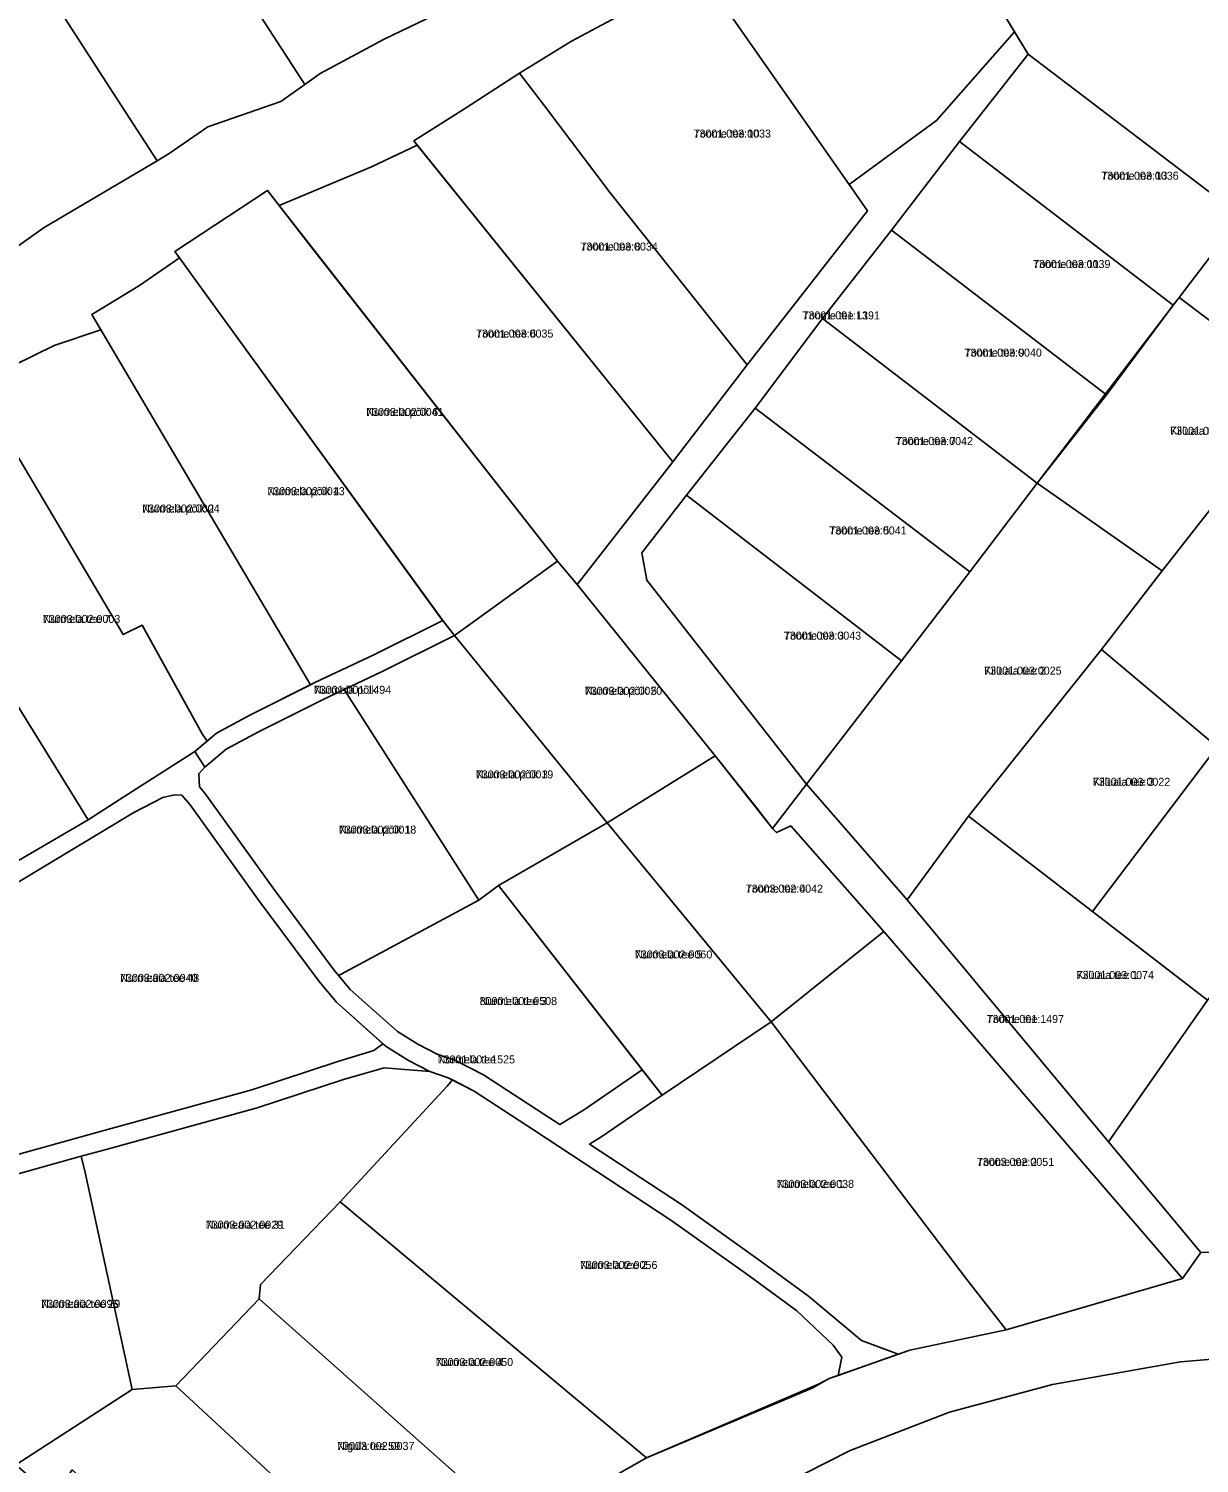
# Model space of a CAD drawing. Extents: x 524000 to 564260, y 6469338 to 6496391.
# Drawn here: x 527061.2 to 527280.6, y 6477525.9 to 6477794.8 of the extents above; entities that cross this region are included whole.
import ezdxf

# ---------------------------------------------------------------- set-up
doc = ezdxf.new("R2010")
doc.units = 0
for name, color, linetype in [('L_AADRESS', 7, 'Continuous'), ('PIIR', 7, 'Continuous'), ('TUNNUS', 7, 'Continuous')]:
    doc.layers.add(name, color=color, linetype=linetype)

msp = doc.modelspace()

# ---------------------------------------------------------------- linework, layer by layer
at = {"layer": 'PIIR'}
for points in [[(527068.69, 6477906.14), (527130.5, 6477810.53), (527138.62, 6477797.97), (527127.79, 6477792.82), (527115.83, 6477786.37), (527112.92, 6477784.31), (527104.79, 6477796.89), (527045.95, 6477887.9)], [(527045.95, 6477887.9), (527104.79, 6477796.89), (527112.92, 6477784.31), (527108.42, 6477781.12), (527094.74, 6477776.35), (527087.52, 6477771.35), (527085.25, 6477770.01), (527077.11, 6477782.59), (527021.72, 6477868.28)], [(527021.72, 6477868.28), (527077.11, 6477782.59), (527085.25, 6477770.01), (527064.12, 6477757.5), (527057.25, 6477752.65), (527056.18, 6477751.87), (527048.35, 6477764.63), (526997.09, 6477848.14)], [(527266.58, 6477860.55), (527270.02, 6477853.57), (527305.23, 6477782.18), (527288.4, 6477759.62), (527248.48, 6477789.96), (527229.03, 6477822.06), (527224.3, 6477829.87)], [(527224.3, 6477829.87), (527229.03, 6477822.06), (527245.93, 6477794.14), (527231.3, 6477777.56), (527214.95, 6477765.58), (527190.7, 6477800.22), (527187.28, 6477805.1), (527195.12, 6477809.32), (527210.56, 6477819.4)], [(527187.28, 6477805.1), (527190.7, 6477800.22), (527214.95, 6477765.58), (527218.37, 6477760.64), (527195.82, 6477731.76), (527170.17, 6477763.97), (527157.85, 6477780.28), (527153.2, 6477786.44), (527162.89, 6477792.39), (527171.34, 6477796.93)], [(527189.84, 6477658.5), (527163.95, 6477690.58), (527181.89, 6477713.57), (527195.82, 6477731.76), (527218.37, 6477760.64), (527214.95, 6477765.58), (527231.3, 6477777.56), (527245.93, 6477794.14), (527248.48, 6477789.96), (527235.64, 6477773.63), (527222.86, 6477757.03), (527209.95, 6477740.46), (527197.34, 6477723.64), (527184.5, 6477707.33), (527176.12, 6477696.54), (527177.03, 6477691.41), (527206.94, 6477653.19), (527200.56, 6477644.84), (527197.69, 6477648.62)], [(527248.48, 6477789.96), (527288.4, 6477759.62), (527276.79, 6477744.38), (527275.7, 6477742.96), (527235.64, 6477773.63)], [(527143.07, 6477779.88), (527153.2, 6477786.44), (527157.85, 6477780.28), (527170.17, 6477763.97), (527195.82, 6477731.76), (527181.89, 6477713.57), (527133.36, 6477773.72)], [(527305.23, 6477782.18), (527324.08, 6477757.66), (527300.02, 6477726.9), (527276.79, 6477744.38), (527288.4, 6477759.62)], [(527125.43, 6477768.89), (527133.99, 6477772.93), (527181.89, 6477713.57), (527163.95, 6477690.58), (527160.28, 6477694.97), (527108.15, 6477761.62)], [(527235.64, 6477773.63), (527275.7, 6477742.96), (527263.16, 6477726.16), (527222.86, 6477757.03)], [(527088.6, 6477753.02), (527105.94, 6477764.46), (527113.9, 6477754.21), (527160.28, 6477694.97), (527140.98, 6477681.05), (527138.46, 6477684.3), (527093.32, 6477746.47)], [(527222.86, 6477757.03), (527263.16, 6477726.16), (527250.21, 6477709.58), (527209.95, 6477740.46)], [(527081.95, 6477746.64), (527089.44, 6477751.81), (527093.32, 6477746.47), (527138.8, 6477683.87), (527125.88, 6477677.42), (527114.82, 6477672.2), (527114.02, 6477671.8), (527076.07, 6477736.03), (527073.02, 6477741.2)], [(527250.21, 6477709.58), (527276.79, 6477744.38), (527300.02, 6477726.9), (527288.08, 6477711.67), (527273.59, 6477693.17)], [(527209.95, 6477740.46), (527250.21, 6477709.58), (527237.54, 6477692.99), (527197.34, 6477723.64)], [(527050.91, 6477728.01), (527065.98, 6477735.39), (527074.71, 6477738.34), (527076.07, 6477736.03), (527114.02, 6477671.8), (527102.76, 6477666.17), (527096.41, 6477662.75), (527094.62, 6477661.25), (527093.73, 6477662.6), (527082.49, 6477682.97), (527078.87, 6477681.22), (527055.88, 6477720.07)], [(527033.11, 6477709.77), (527037.79, 6477712.63), (527045.06, 6477726.1), (527049.58, 6477730.12), (527055.88, 6477720.07), (527078.87, 6477681.22), (527082.49, 6477682.97), (527093.73, 6477662.6), (527094.62, 6477661.25), (527092.3, 6477659.3), (527079.19, 6477650.92), (527072.35, 6477646.49), (527035.82, 6477705.55)], [(527197.34, 6477723.64), (527237.54, 6477692.99), (527224.78, 6477676.3), (527184.5, 6477707.33)], [(527012.25, 6477696.65), (527016.89, 6477699.87), (527033.11, 6477709.77), (527035.82, 6477705.55), (527072.35, 6477646.49), (527051.39, 6477634.3), (527015.45, 6477691.74)], [(527273.59, 6477693.17), (527288.08, 6477711.67), (527309.2, 6477692.83), (527284.7, 6477661.21), (527283.91, 6477660.2), (527262.26, 6477678.4)], [(527176.12, 6477696.54), (527184.5, 6477707.33), (527224.78, 6477676.3), (527206.94, 6477653.19), (527177.03, 6477691.41)], [(527273.59, 6477693.17), (527262.26, 6477678.4), (527237.33, 6477647.17), (527225.84, 6477631.5), (527206.94, 6477653.19), (527224.78, 6477676.3), (527237.54, 6477692.99), (527250.21, 6477709.58)], [(527140.98, 6477681.05), (527160.28, 6477694.97), (527163.95, 6477690.58), (527189.84, 6477658.5), (527169.63, 6477645.9)], [(527094.19, 6477656.35), (527092.3, 6477659.3), (527096.41, 6477662.75), (527102.76, 6477666.17), (527114.82, 6477672.2), (527125.88, 6477677.42), (527138.8, 6477683.87), (527140.98, 6477681.05), (527127.41, 6477674.27), (527116.35, 6477669.05), (527104.37, 6477663.07), (527098.23, 6477659.76)], [(527140.98, 6477681.05), (527169.63, 6477645.9), (527149.26, 6477634.18), (527145.57, 6477631.45), (527120.34, 6477670.91), (527127.41, 6477674.27)], [(527262.26, 6477678.4), (527283.91, 6477660.2), (527260.55, 6477629.3), (527237.33, 6477647.17)], [(527094.18, 6477651.5), (527093.18, 6477652.67), (527093.07, 6477655.11), (527094.19, 6477656.35), (527098.23, 6477659.76), (527104.37, 6477663.07), (527116.35, 6477669.05), (527120.34, 6477670.91), (527145.57, 6477631.45), (527119.78, 6477617.58), (527119.25, 6477617.33), (527118.38, 6477618.39), (527106.99, 6477633.69)], [(527283.91, 6477660.2), (527284.7, 6477661.21), (527303.16, 6477646.66), (527309.29, 6477646.1), (527284.74, 6477615.95), (527282.09, 6477612.69), (527260.55, 6477629.3)], [(527189.84, 6477658.5), (527200.56, 6477644.84), (527201.34, 6477644.1), (527204.02, 6477645.36), (527221.47, 6477625.55), (527200.35, 6477608.66), (527169.63, 6477645.9)], [(527049.14, 6477582.17), (527043.65, 6477607.26), (527039.32, 6477621.44), (527053.45, 6477630.04), (527052.83, 6477631.31), (527059.2, 6477634.82), (527080.9, 6477647.87), (527086.34, 6477650.7), (527088.51, 6477651.18), (527089.89, 6477651.11), (527091.43, 6477649.33), (527104.16, 6477631.62), (527115.62, 6477616.22), (527118.89, 6477612.29), (527127.58, 6477604.53), (527125.89, 6477603.25), (527119.15, 6477601.17), (527102.99, 6477595.86), (527074.81, 6477588.11), (527049.41, 6477581.07)], [(527201.34, 6477644.1), (527200.56, 6477644.84), (527206.94, 6477653.19), (527225.84, 6477631.5), (527263.58, 6477586.14), (527280.85, 6477565.38), (527277.39, 6477560.55), (527221.47, 6477625.55), (527204.02, 6477645.36)], [(527169.63, 6477645.9), (527200.35, 6477608.66), (527179.88, 6477594.87), (527149.26, 6477634.18)], [(527237.33, 6477647.17), (527260.55, 6477629.3), (527282.09, 6477612.69), (527263.58, 6477586.14), (527225.84, 6477631.5)], [(527176.19, 6477599.61), (527165.19, 6477592.06), (527160.7, 6477589.38), (527157.71, 6477591.35), (527146.41, 6477598.69), (527141.18, 6477601.38), (527137.72, 6477602.54), (527134.09, 6477604.43), (527130.3, 6477606.79), (527121.41, 6477614.72), (527119.25, 6477617.33), (527119.78, 6477617.58), (527145.57, 6477631.45), (527149.26, 6477634.18)], [(527237.01, 6477560.31), (527200.35, 6477608.66), (527221.47, 6477625.55), (527277.39, 6477560.55), (527244.38, 6477550.91)], [(527284.74, 6477615.95), (527313.28, 6477594.45), (527293.22, 6477567.9), (527291.37, 6477565.45), (527280.85, 6477565.38), (527263.58, 6477586.14), (527282.09, 6477612.69)], [(527168.43, 6477587), (527179.88, 6477594.87), (527200.35, 6477608.66), (527237.01, 6477560.31), (527244.38, 6477550.91), (527226.35, 6477547.12), (527224.16, 6477546.35), (527217.25, 6477548.93), (527207.32, 6477557.24), (527198.29, 6477563.86), (527183.51, 6477574.37), (527166.27, 6477585.71)], [(527080.58, 6477539.74), (527071.78, 6477580.42), (527071.03, 6477583.43), (527075.74, 6477584.73), (527104, 6477592.51), (527120.17, 6477597.83), (527127.79, 6477599.98), (527136.34, 6477599.31), (527139.82, 6477598.14), (527140.62, 6477597.73), (527139.6, 6477596.55), (527119.54, 6477574.91), (527104.61, 6477559.39), (527104.36, 6477556.74), (527088.74, 6477540.41)], [(527139.6, 6477596.55), (527140.62, 6477597.73), (527144.65, 6477595.66), (527155.79, 6477588.42), (527181.53, 6477571.49), (527196.24, 6477561.02), (527205.16, 6477554.48), (527211.98, 6477548.02), (527213.58, 6477545.77), (527212.88, 6477542.37), (527211.21, 6477541.78), (527209.32, 6477540.76), (527176.97, 6477526.91), (527119.54, 6477574.91)], [(527047.22, 6477573.95), (527046.47, 6477576.6), (527071.03, 6477583.43), (527071.78, 6477580.42), (527080.58, 6477539.74), (527058.76, 6477525.63)], [(527104.61, 6477559.39), (527119.54, 6477574.91), (527176.97, 6477526.91), (527152.9, 6477513.32), (527147.81, 6477518.11), (527104.36, 6477556.74)], [(527104.36, 6477556.74), (527147.81, 6477518.11), (527152.9, 6477513.32), (527138.49, 6477505.41), (527132.38, 6477500.06), (527088.74, 6477540.41)], [(526966.03, 6477334.3), (526961.42, 6477339.2), (527133.49, 6477486.9), (527215.14, 6477528.28), (527233.77, 6477535.48), (527253.08, 6477540.66), (527277.05, 6477544.9), (527294.83, 6477546.38), (527443.67, 6477546.48), (527421.21, 6477079.93), (527421.11, 6477077.85), (527474.06, 6477077.6), (527467.53, 6476773.03), (527467.51, 6476771.43), (527328.08, 6476772.76), (527278.75, 6476772.87), (527278.76, 6476774.48), (527271.46, 6477078.71), (526973.49, 6477080.13), (526973.01, 6477080.54), (526970.49, 6477216.24), (526968.64, 6477315.82), (526968.61, 6477324.1), (526968.15, 6477329.93)], [(527065.57, 6477518.84), (527062.16, 6477522.74), (527061.47, 6477523.32), (527058.76, 6477525.63), (527080.58, 6477539.74), (527088.74, 6477540.41), (527132.38, 6477500.06), (527113.17, 6477484.7), (527109.22, 6477488.12), (527069.33, 6477524.66)]]:
    msp.add_lwpolyline(points, close=True, dxfattribs=at)
for points in [[(526888.32, 6477649.68), (526950.85, 6477675.06), (526957.96, 6477678.04), (526973.04, 6477689.13), (526978.77, 6477693.69), (526986.78, 6477700.05), (526995.46, 6477709.06), (527020.5, 6477725.25), (527028.95, 6477732.03), (527056.18, 6477751.87), (527057.25, 6477752.65), (527064.12, 6477757.5), (527085.25, 6477770.01), (527087.52, 6477771.35), (527094.74, 6477776.35), (527108.42, 6477781.12), (527112.92, 6477784.31), (527115.83, 6477786.37), (527127.79, 6477792.82), (527138.62, 6477797.97)], [(527171.34, 6477796.93), (527162.89, 6477792.39), (527153.2, 6477786.44), (527143.07, 6477779.88), (527133.36, 6477773.72), (527133.99, 6477772.93), (527125.43, 6477768.89), (527108.15, 6477761.62), (527105.94, 6477764.46), (527088.6, 6477753.02), (527089.44, 6477751.81), (527081.95, 6477746.64), (527073.02, 6477741.2), (527074.71, 6477738.34), (527065.98, 6477735.39), (527050.91, 6477728.01)], [(527051.39, 6477634.3), (527072.35, 6477646.49), (527079.19, 6477650.92), (527092.3, 6477659.3), (527094.19, 6477656.35), (527093.07, 6477655.11), (527093.18, 6477652.67), (527094.18, 6477651.5), (527106.99, 6477633.69), (527118.38, 6477618.39), (527121.41, 6477614.72), (527130.3, 6477606.79), (527134.09, 6477604.43), (527137.72, 6477602.54), (527141.18, 6477601.38), (527146.41, 6477598.69), (527157.71, 6477591.35), (527160.7, 6477589.38), (527165.19, 6477592.06), (527176.19, 6477599.61), (527179.88, 6477594.87), (527168.43, 6477587), (527166.27, 6477585.71), (527183.51, 6477574.37), (527198.29, 6477563.86), (527207.32, 6477557.24), (527217.25, 6477548.93), (527224.16, 6477546.35), (527212.88, 6477542.37), (527213.58, 6477545.77), (527211.98, 6477548.02), (527205.16, 6477554.48), (527196.24, 6477561.02), (527181.53, 6477571.49), (527155.79, 6477588.42), (527144.65, 6477595.66), (527139.82, 6477598.14), (527136.34, 6477599.31), (527132.35, 6477601.39), (527128.19, 6477603.98), (527118.89, 6477612.29), (527115.62, 6477616.22), (527104.16, 6477631.62), (527091.43, 6477649.33), (527089.89, 6477651.11), (527088.51, 6477651.18), (527086.34, 6477650.7), (527080.9, 6477647.87), (527059.2, 6477634.82)], [(527049.41, 6477581.07), (527074.81, 6477588.11), (527102.99, 6477595.86), (527119.15, 6477601.17), (527125.89, 6477603.25), (527127.58, 6477604.53), (527128.19, 6477603.98), (527132.35, 6477601.39), (527136.34, 6477599.31), (527127.79, 6477599.98), (527120.17, 6477597.83), (527104, 6477592.51), (527075.74, 6477584.73), (527071.03, 6477583.43), (527046.47, 6477576.6)], [(527152.9, 6477513.32), (527176.97, 6477526.91), (527208, 6477540), (527211.21, 6477541.78), (527226.35, 6477547.12), (527244.38, 6477550.91), (527277.39, 6477560.55), (527280.85, 6477565.38), (527291.37, 6477565.45), (527341.17, 6477565.77), (527367.3, 6477565.93), (527438.89, 6477565.66), (527438.18, 6477563.85), (527522.25, 6477564.25)], [(527943.01, 6477552.48), (527756.15, 6477554.51), (527586, 6477554), (527444, 6477554), (527443.87, 6477550.59), (527443.67, 6477546.48), (527294.83, 6477546.38), (527277.05, 6477544.89), (527253.08, 6477540.66), (527233.77, 6477535.48), (527215.14, 6477528.28), (527133.49, 6477486.9), (526961.42, 6477339.2), (526960, 6477337.75), (526956.13, 6477334.52), (526951.59, 6477330.73), (526950.53, 6477329.81), (526924.88, 6477308.1), (526899.56, 6477286.58), (526736, 6477147)]]:
    msp.add_lwpolyline(points, dxfattribs=at)

# ---------------------------------------------------------------- texts
at = {"layer": 'L_AADRESS'}
for s, p in [('Toome tee 10', (527185.79, 6477774.35)), ('Toome tee 13', (527262.2, 6477766.46)), ('Toome tee 8', (527164.59, 6477753.18)), ('Toome tee 11', (527249.41, 6477749.9)), ('Toome tee L1', (527206.21, 6477740.28)), ('Toome tee 6', (527145.02, 6477736.87)), ('Toome tee 9', (527236.56, 6477733.3)), ('Nurmela põik 6', (527124.44, 6477722.18)), ('Toome tee 7', (527223.65, 6477716.73)), ('Kiiluaia tee 4', (527275.12, 6477718.65)), ('Nurmela põik 4', (527105.91, 6477707.33)), ('Nurmela põik 2', (527082.46, 6477704.08)), ('Toome tee 5', (527211.22, 6477699.97)), ('Nurmela tee 7', (527063.86, 6477683.39)), ('Toome tee 3', (527202.7, 6477680.26)), ('Kiiluaia tee 2', (527240.27, 6477673.7)), ('Nurmela põik', (527114.62, 6477670.11)), ('Nurmela põik 5', (527165.41, 6477669.92)), ('Nurmela põik 3', (527144.99, 6477654.25)), ('Kiiluaia tee 3', (527260.62, 6477652.87)), ('Nurmela põik 1', (527119.32, 6477643.9)), ('Toome tee 4', (527195.55, 6477632.85)), ('Nurmela tee 5', (527174.8, 6477620.51)), ('Nurmeaia tee 48', (527078.32, 6477616.12)), ('Kiiluaia tee 1', (527257.57, 6477616.66)), ('Nurmela tee 3', (527145.71, 6477611.78)), ('Toome tee', (527240.71, 6477608.41)), ('Nurmela tee', (527137.83, 6477600.84)), ('Toome tee 2', (527238.87, 6477581.63)), ('Nurmela tee 1', (527201.36, 6477577.51)), ('Nurmeaia tee 31', (527094.37, 6477569.86)), ('Nurmela tee 2', (527164.51, 6477562.32)), ('Nurmeaia tee 29', (527063.52, 6477555.03)), ('Nurmela tee 4', (527137.47, 6477544.12)), ('Nigula tee 59', (527118.98, 6477528.4))]:
    msp.add_text(s, height=1.5, dxfattribs=at).set_placement(p)
at = {"layer": 'TUNNUS'}
for s, p in [('73001:003:0033', (527185.79, 6477774.35)), ('73001:003:0036', (527262.2, 6477766.46)), ('73001:003:0034', (527164.59, 6477753.18)), ('73001:003:0039', (527249.41, 6477749.9)), ('73001:001:1391', (527206.21, 6477740.28)), ('73001:003:0035', (527145.02, 6477736.87)), ('73001:003:0040', (527236.56, 6477733.3)), ('73003:002:0041', (527124.44, 6477722.18)), ('73001:003:0042', (527223.65, 6477716.73)), ('73001:003:0003', (527275.12, 6477718.65)), ('73003:002:0013', (527105.91, 6477707.33)), ('73003:002:0004', (527082.46, 6477704.08)), ('73001:003:0041', (527211.22, 6477699.97)), ('73003:002:0003', (527063.86, 6477683.39)), ('73001:003:0043', (527202.7, 6477680.26)), ('73001:003:0025', (527240.27, 6477673.7)), ('73001:001:1494', (527114.62, 6477670.11)), ('73003:002:0020', (527165.41, 6477669.92)), ('73003:002:0019', (527144.99, 6477654.25)), ('73001:003:0022', (527260.62, 6477652.87)), ('73003:002:0018', (527119.32, 6477643.9)), ('73003:002:0042', (527195.55, 6477632.85)), ('73003:002:0060', (527174.8, 6477620.51)), ('73003:002:0040', (527078.32, 6477616.12)), ('73001:003:0074', (527257.57, 6477616.66)), ('80901:001:0508', (527145.71, 6477611.78)), ('73001:001:1497', (527240.71, 6477608.41)), ('73001:001:1525', (527137.83, 6477600.84)), ('73003:002:0051', (527238.87, 6477581.63)), ('73003:002:0038', (527201.36, 6477577.51)), ('73003:002:0029', (527094.37, 6477569.86)), ('73003:002:0056', (527164.51, 6477562.32)), ('73003:002:0096', (527063.52, 6477555.03)), ('73003:002:0050', (527137.47, 6477544.12)), ('73003:002:0037', (527118.98, 6477528.4))]:
    msp.add_text(s, height=1.5, dxfattribs=at).set_placement(p)

doc.saveas('drawing.dxf')
